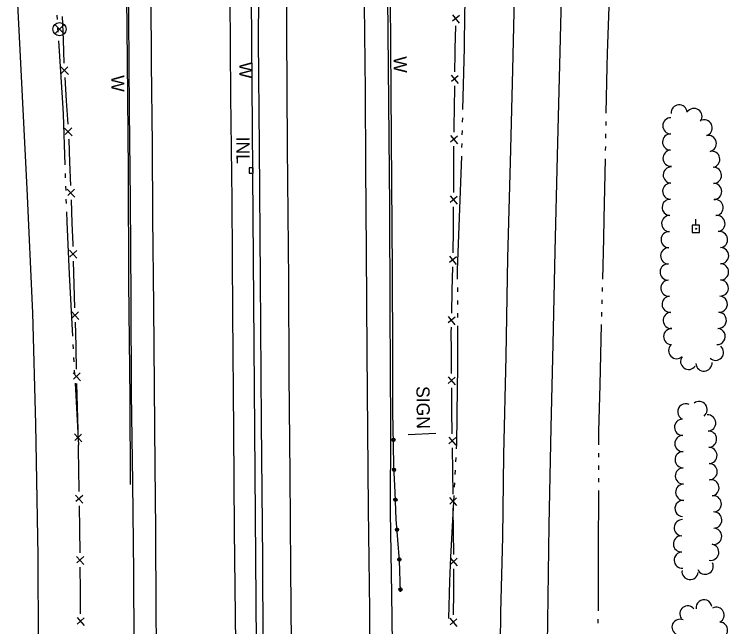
# Model space of a CAD drawing. Extents: x 589250 to 1188077, y 162953 to 363065.
# Drawn here: x 594129.9 to 594456.9, y 169760.3 to 170040.7 of the extents above; entities that cross this region are included whole.
import ezdxf

# ---------------------------------------------------------------- set-up
doc = ezdxf.new("R2010")
doc.units = 0
for name, color, linetype in [('E_BMGRD_P', 7, 'Continuous'), ('E_DRN', 7, 'Continuous'), ('E_DRN_Pipe', 7, 'Continuous'), ('E_DRN_SS_UG', 7, 'Continuous'), ('E_DRN_Text', 7, 'Continuous'), ('E_FEN_P', 7, 'Continuous'), ('E_LAND_TreeLine_P', 7, 'Continuous'), ('E_RDWY', 7, 'Continuous'), ('E_RDWY_Gravel', 7, 'Continuous'), ('E_SGN', 7, 'Continuous'), ('E_SGN_Text', 7, 'Continuous'), ('E_SIG', 7, 'Continuous'), ('E_UTL_EPowerPole', 7, 'Continuous'), ('E_WAL', 7, 'Continuous'), ('E_WAL_Text', 7, 'Continuous'), ('E_WTR_FlowLine', 7, 'Continuous')]:
    doc.layers.add(name, color=color, linetype=linetype)

msp = doc.modelspace()

# ---------------------------------------------------------------- linework, layer by layer
at = {"layer": 'E_BMGRD_P'}
for p, q in [((594303.52, 169843.67), (594303.16, 169858.43)), ((594303.56, 169833.83), (594303.52, 169843.67)), ((594304.24, 169821.84), (594303.56, 169833.83)), ((594304.68, 169809.49), (594304.24, 169821.84)), ((594306.19, 169790.56), (594304.68, 169809.49)), ((594306.67, 169776.16), (594306.19, 169790.56))]:
    msp.add_line(p, q, dxfattribs=at)
for centre, major_axis, ratio in [((594303.47, 169845.84), (0.002, -0.8), 0.911661), ((594303.47, 169845.84), (0.001, -0.403), 0.911661), ((594303.66, 169832.12), (0.023, 0.799), 0.911246), ((594303.66, 169832.12), (0.012, 0.403), 0.911246), ((594304.36, 169818.42), (0.023, 0.799), 0.911373), ((594304.36, 169818.42), (0.011, 0.403), 0.911373), ((594305.06, 169804.71), (0.01, -0.8), 0.911816), ((594305.06, 169804.71), (0.005, -0.403), 0.911816), ((594306.15, 169791.03), (0.01, -0.8), 0.911816), ((594306.15, 169791.03), (0.005, -0.403), 0.911816), ((594306.63, 169777.31), (0.026, -0.799), 0.911732), ((594306.63, 169777.31), (0.013, -0.403), 0.911732)]:
    msp.add_ellipse(centre, major_axis=major_axis, ratio=ratio, dxfattribs=at)
at = {"layer": 'E_DRN'}
for p, q in [((594239.2, 169970.45), (594237.36, 169970.44)), ((594237.36, 169970.44), (594237.38, 169967.95)), ((594239.21, 169967.96), (594239.2, 169970.45)), ((594237.38, 169967.95), (594239.21, 169967.96))]:
    msp.add_line(p, q, dxfattribs=at)
at = {"layer": 'E_DRN_Pipe'}
msp.add_line((594239.14, 169968.53), (594236.28, 170334.67), dxfattribs=at)
at = {"layer": 'E_DRN_SS_UG'}
msp.add_line((594241.45, 169671.17), (594239.14, 169967.85), dxfattribs=at)
at = {"layer": 'E_FEN_P'}
for p, q in [((594330.44, 170040.42), (594333.56, 170036.68)), ((594333.64, 170040.19), (594330.45, 170037.49)), ((594151.83, 170039.72), (594152.22, 170029.02)), ((594331.82, 170035.48), (594331.59, 170024.94)), ((594152.22, 170029.02), (594152.6, 170018.32)), ((594331.59, 170024.94), (594331.54, 170022.66)), ((594331.54, 170022.66), (594331.42, 170014.39)), ((594151.15, 170016.58), (594154.63, 170013.06)), ((594154.4, 170016.61), (594151.4, 170013.61)), ((594152.96, 170011.7), (594153.64, 170001.02)), ((594329.91, 170012.79), (594333.06, 170009.06)), ((594333.11, 170012.57), (594329.93, 170009.85)), ((594331.32, 170007.86), (594331.15, 169997.31)), ((594153.64, 170001.02), (594154.32, 169990.33)), ((594331.15, 169997.31), (594331.04, 169989.97)), ((594152.93, 169988.59), (594156.4, 169985.08)), ((594156.18, 169988.63), (594153.18, 169985.63)), ((594331.04, 169989.97), (594331.02, 169986.76)), ((594329.53, 169985.15), (594332.71, 169981.45)), ((594332.73, 169984.96), (594329.58, 169982.21)), ((594154.74, 169983.72), (594154.78, 169983.15)), ((594154.78, 169983.15), (594155.17, 169973.02)), ((594330.98, 169980.23), (594330.93, 169969.68)), ((594155.17, 169973.02), (594155.59, 169962.32)), ((594330.93, 169969.68), (594330.87, 169959.13)), ((594154.16, 169960.62), (594157.55, 169957.02)), ((594157.41, 169960.58), (594154.34, 169957.65)), ((594155.85, 169955.7), (594156.27, 169945)), ((594329.38, 169957.52), (594332.56, 169953.82)), ((594332.58, 169957.33), (594329.43, 169954.58)), ((594330.83, 169952.6), (594330.77, 169942.57)), ((594156.27, 169945), (594156.64, 169935.46)), ((594330.76, 169942.05), (594330.54, 169931.51)), ((594330.77, 169942.57), (594330.76, 169942.05)), ((594156.64, 169935.46), (594156.68, 169934.31)), ((594155.23, 169932.62), (594158.58, 169928.98)), ((594158.48, 169932.54), (594155.38, 169929.64)), ((594329.03, 169929.91), (594332.15, 169926.17)), ((594332.22, 169929.68), (594329.03, 169926.98)), ((594156.87, 169927.68), (594157.19, 169916.98)), ((594330.4, 169924.98), (594330.17, 169914.43)), ((594157.19, 169916.98), (594157.5, 169906.28)), ((594330.17, 169914.43), (594329.95, 169903.88)), ((594156.05, 169904.59), (594159.4, 169900.96)), ((594159.3, 169904.51), (594156.2, 169901.62)), ((594157.69, 169899.66), (594158.01, 169888.95)), ((594328.44, 169902.29), (594331.56, 169898.55)), ((594331.63, 169902.05), (594328.44, 169899.36)), ((594329.81, 169897.35), (594329.77, 169895.16)), ((594329.77, 169895.16), (594329.83, 169886.8)), ((594158.01, 169888.95), (594158.04, 169887.76)), ((594158.04, 169887.76), (594158.26, 169878.25)), ((594329.83, 169886.8), (594329.91, 169876.25)), ((594156.8, 169876.57), (594160.13, 169872.92)), ((594160.05, 169876.47), (594156.94, 169873.6)), ((594328.44, 169874.62), (594331.67, 169870.97)), ((594331.64, 169874.48), (594328.53, 169871.69)), ((594158.41, 169871.63), (594158.66, 169860.92)), ((594329.95, 169869.72), (594330.01, 169861.88)), ((594158.66, 169860.92), (594158.91, 169850.22)), ((594330.01, 169861.88), (594330.05, 169859.17)), ((594330.05, 169859.17), (594330.18, 169848.63)), ((594157.44, 169848.54), (594160.78, 169844.89)), ((594160.69, 169848.44), (594157.58, 169845.57)), ((594328.73, 169846.98), (594331.97, 169843.35)), ((594331.93, 169846.86), (594328.83, 169844.05)), ((594159.06, 169843.6), (594159.12, 169840.84)), ((594159.12, 169840.84), (594159.25, 169832.89)), ((594330.27, 169842.1), (594330.4, 169831.55)), ((594159.25, 169832.89), (594159.43, 169822.19)), ((594330.4, 169831.55), (594330.54, 169821)), ((594157.95, 169820.52), (594161.26, 169816.84)), ((594161.2, 169820.4), (594158.07, 169817.54)), ((594329.08, 169819.36), (594332.32, 169815.72)), ((594332.28, 169819.23), (594329.18, 169816.43)), ((594159.53, 169815.56), (594159.71, 169804.86)), ((594330.62, 169814.47), (594330.74, 169803.92)), ((594159.71, 169804.86), (594159.88, 169794.15)), ((594330.74, 169803.92), (594330.86, 169793.37)), ((594158.41, 169792.48), (594161.72, 169788.81)), ((594161.66, 169792.36), (594158.53, 169789.51)), ((594329.41, 169791.73), (594332.65, 169788.09)), ((594332.61, 169791.6), (594329.51, 169788.8)), ((594159.96, 169787.53), (594160.03, 169776.82)), ((594330.94, 169786.72), (594330.87, 169776.29)), ((594330.94, 169786.84), (594330.94, 169786.72)), ((594160.03, 169776.82), (594160.11, 169766.11)), ((594330.87, 169776.29), (594330.8, 169765.74)), ((594158.62, 169764.46), (594161.89, 169760.75)), ((594161.87, 169764.31), (594158.7, 169761.48)), ((594329.31, 169764.13), (594332.49, 169760.43)), ((594332.51, 169763.94), (594329.36, 169761.19))]:
    msp.add_line(p, q, dxfattribs=at)
at = {"layer": 'E_LAND_TreeLine_P'}
for centre, radius, start, end in [((594434.21, 169995.57), 3.7, 5.3349, 185.3349), ((594440.97, 169993.88), 3.7, 325.9442, 145.9442), ((594430.4, 169989.64), 3.7, 89.027, 269.027), ((594445.66, 169988.69), 3.7, 285.5571, 105.5571), ((594430.27, 169982.23), 3.7, 89.027, 269.027), ((594447.55, 169981.53), 3.7, 282.2461, 102.2461), ((594430.49, 169974.83), 3.7, 93.3221, 273.3221), ((594449.12, 169974.29), 3.7, 282.2461, 102.2461), ((594430.59, 169967.09), 3.7, 88.1337, 268.1337), ((594449.88, 169966.96), 3.7, 270.9362, 90.9362), ((594430.35, 169959.68), 3.7, 88.1337, 268.1337), ((594450.01, 169959.56), 3.7, 270.9362, 90.9362), ((594430.11, 169952.28), 3.7, 88.1337, 268.1337), ((594450.68, 169952.18), 3.7, 275.8353, 95.8353), ((594429.87, 169944.88), 3.7, 88.1337, 268.1337), ((594451.52, 169944.83), 3.7, 279.0663, 99.0663), ((594429.63, 169937.48), 3.7, 88.1337, 268.1337), ((594452.69, 169937.51), 3.7, 279.0663, 99.0663), ((594429.39, 169930.07), 3.7, 88.1337, 268.1337), ((594453.18, 169930.15), 3.7, 269.8129, 89.8129), ((594429.15, 169922.67), 3.7, 88.1337, 268.1337), ((594453.16, 169922.74), 3.7, 269.8129, 89.8129), ((594453.06, 169915.34), 3.7, 266.3361, 86.3361), ((594429.52, 169915.28), 3.7, 94.1607, 274.1607), ((594430.05, 169907.9), 3.7, 94.1607, 274.1607), ((594452.59, 169907.95), 3.7, 266.3361, 86.3361), ((594430.59, 169900.51), 3.7, 94.1607, 274.1607), ((594452.11, 169900.56), 3.7, 266.3361, 86.3361), ((594430.78, 169893.11), 3.7, 88.2099, 268.2099), ((594451.64, 169893.17), 3.7, 266.3361, 86.3361), ((594433.05, 169886.68), 3.7, 134.2005, 314.2005), ((594450.82, 169885.92), 3.7, 227.9111, 47.9111), ((594438.54, 169881.76), 3.7, 144.9088, 324.9088), ((594445.57, 169881), 3.7, 184.116, 4.116), ((594437.24, 169858.68), 3.72, 64.3711, 244.3711), ((594443.32, 169859.67), 3.72, 307.8061, 127.8061), ((594447.26, 169853.56), 3.72, 272.9111, 92.9111), ((594435.79, 169851.58), 3.72, 90.9362, 270.9362), ((594435.91, 169844.15), 3.72, 90.9362, 270.9362), ((594447.64, 169846.13), 3.72, 272.9111, 92.9111), ((594447.81, 169838.7), 3.72, 270.9362, 90.9362), ((594436.03, 169836.71), 3.72, 90.9362, 270.9362), ((594447.93, 169831.26), 3.72, 270.9362, 90.9362), ((594436.15, 169829.28), 3.72, 90.9362, 270.9362), ((594448.75, 169823.88), 3.72, 278.2419, 98.2419), ((594436.27, 169821.84), 3.72, 90.9362, 270.9362), ((594435.99, 169814.42), 3.72, 86.5375, 266.5375), ((594449.82, 169816.53), 3.72, 278.2419, 98.2419), ((594450.03, 169809.1), 3.72, 270.9362, 90.9362), ((594435.61, 169805.6), 3.72, 87.2448, 267.2448), ((594449.97, 169801.68), 3.72, 259.6263, 79.6263), ((594435.28, 169798.17), 3.72, 92.7261, 272.7261), ((594448.63, 169794.36), 3.72, 259.6263, 79.6263), ((594435.64, 169790.74), 3.72, 92.7261, 272.7261), ((594446.09, 169787.99), 3.72, 204.1348, 24.1348), ((594439.21, 169785.54), 3.72, 173.8112, 353.8112), ((594445.59, 169768.99), 3.62, 9.0663, 189.0663), ((594438.11, 169766.18), 3.62, 37.8061, 217.8061), ((594451.18, 169765.6), 3.62, 297.5012, 117.5012), ((594434.51, 169760.05), 3.62, 65.59, 245.59), ((594452.76, 169758.72), 3.62, 267.3599, 87.3599)]:
    msp.add_arc(centre, radius, start, end, dxfattribs=at)
at = {"layer": 'E_RDWY'}
for p, q in [((594133.1, 170015.26), (594129.89, 170076.56)), ((594254.22, 170077.86), (594254.52, 170032.66)), ((594380.63, 170067.84), (594379.64, 170023.43)), ((594192.32, 170054.05), (594192.55, 170018.28)), ((594358.89, 170054.26), (594357.94, 170015.23)), ((594228.51, 170049.52), (594228.88, 170003.19)), ((594289.99, 170045.02), (594290.5, 170005.63)), ((594254.52, 170032.66), (594254.8, 169979.85)), ((594379.64, 170023.43), (594378.34, 169975.84)), ((594192.55, 170018.28), (594192.94, 169981.06)), ((594135.72, 169960.73), (594133.1, 170015.26)), ((594357.94, 170015.23), (594356.8, 169972.92)), ((594290.5, 170005.63), (594290.64, 169970.91)), ((594228.88, 170003.19), (594229.53, 169955.59)), ((594192.94, 169981.06), (594193.14, 169947.57)), ((594254.8, 169979.85), (594255.36, 169918.86)), ((594378.34, 169975.84), (594377.34, 169932.17)), ((594356.8, 169972.92), (594355.56, 169929.12)), ((594290.64, 169970.91), (594290.99, 169932.09)), ((594138.34, 169904.03), (594135.72, 169960.73)), ((594229.53, 169955.59), (594229.74, 169903.62)), ((594193.14, 169947.57), (594193.58, 169907.07)), ((594290.99, 169932.09), (594291.32, 169886.04)), ((594377.34, 169932.17), (594376.45, 169889.6)), ((594355.56, 169929.12), (594354.83, 169884.1)), ((594255.36, 169918.86), (594255.48, 169875.71)), ((594193.58, 169907.07), (594193.84, 169870.19)), ((594139.81, 169852.95), (594138.34, 169904.03)), ((594229.74, 169903.62), (594230.23, 169850)), ((594376.45, 169889.6), (594375.48, 169851.43)), ((594291.32, 169886.04), (594291.92, 169814.2)), ((594354.83, 169884.1), (594353.86, 169838.96)), ((594255.48, 169875.71), (594256.08, 169829.78)), ((594193.84, 169870.19), (594194.21, 169833.77)), ((594140.79, 169792.72), (594139.81, 169852.95)), ((594375.48, 169851.43), (594374.62, 169806.78)), ((594230.23, 169850), (594230.59, 169804.43)), ((594353.86, 169838.96), (594353.37, 169801.29)), ((594194.21, 169833.77), (594194.46, 169804.8)), ((594256.08, 169829.78), (594256.34, 169787.07)), ((594291.92, 169814.2), (594292.4, 169767.86)), ((594194.46, 169804.8), (594194.62, 169767.13)), ((594374.62, 169806.78), (594373.88, 169762.74)), ((594230.59, 169804.43), (594231.17, 169745.69)), ((594353.37, 169801.29), (594352.47, 169766.79)), ((594141.11, 169738), (594140.79, 169792.72)), ((594256.34, 169787.07), (594256.72, 169737.34)), ((594194.62, 169767.13), (594195.04, 169727.65)), ((594292.4, 169767.86), (594292.59, 169721.1)), ((594352.47, 169766.79), (594352.07, 169730.95)), ((594373.88, 169762.74), (594373.25, 169718.95))]:
    msp.add_line(p, q, dxfattribs=at)
at = {"layer": 'E_RDWY_Gravel'}
for p, q in [((594181.78, 170084.34), (594182.16, 170039.34)), ((594300.66, 170052.32), (594301.14, 170000.36)), ((594182.16, 170039.34), (594182.5, 169996.63)), ((594301.14, 170000.36), (594301.55, 169952.6)), ((594182.5, 169996.63), (594182.93, 169955.6)), ((594182.93, 169955.6), (594183.18, 169910.6)), ((594301.55, 169952.6), (594301.82, 169905.46)), ((594183.18, 169910.6), (594183.41, 169867.04)), ((594301.82, 169905.46), (594302.09, 169851.77)), ((594183.41, 169867.04), (594183.96, 169826.25)), ((594302.09, 169851.77), (594302, 169812.78)), ((594183.96, 169826.25), (594184.4, 169784.86)), ((594302, 169812.78), (594302.49, 169775.26)), ((594184.4, 169784.86), (594184.71, 169743.58)), ((594302.49, 169775.26), (594303.11, 169729.61))]:
    msp.add_line(p, q, dxfattribs=at)
at = {"layer": 'E_SGN'}
msp.add_line((594310.19, 169848.26), (594322.77, 169848.9), dxfattribs=at)
at = {"layer": 'E_SIG'}
for points in [[(594152.66, 170036.01), (594148.47, 170031.77)], [(594148.47, 170035.96), (594152.7, 170031.73)]]:
    msp.add_lwpolyline(points, dxfattribs=at)
msp.add_circle((594150.6, 170033.89), 3, dxfattribs=at)
at = {"layer": 'E_UTL_EPowerPole'}
for points in [[(594441.89, 169944.17), (594441.89, 169946.81)], [(594443.57, 169944.17), (594440.21, 169944.17)], [(594440.21, 169944.17), (594440.21, 169940.81)], [(594443.57, 169940.81), (594443.57, 169944.17)], [(594440.21, 169940.81), (594443.57, 169940.81)]]:
    msp.add_lwpolyline(points, dxfattribs=at)
msp.add_circle((594441.92, 169942.49), 0.217, dxfattribs=at)
at = {"layer": 'E_WAL'}
for p, q in [((594181.02, 170069.84), (594181.48, 170019.57)), ((594241.65, 170049.38), (594241.55, 170028.96)), ((594302.32, 170005.17), (594302.11, 170047.41)), ((594241.55, 170028.96), (594241.92, 169979.9)), ((594181.48, 170019.57), (594181.94, 169968.92)), ((594302.65, 169963.42), (594302.32, 170005.17)), ((594241.92, 169979.9), (594242.46, 169919.76)), ((594181.94, 169968.92), (594182.22, 169917.91)), ((594303.06, 169923.35), (594302.65, 169963.42)), ((594303.09, 169885.07), (594303.06, 169923.35)), ((594242.46, 169919.76), (594242.89, 169853.75)), ((594182.22, 169917.91), (594182.72, 169864.89)), ((594303.16, 169858.43), (594303.09, 169885.07)), ((594182.72, 169864.89), (594183, 169825.39)), ((594242.89, 169853.75), (594243.48, 169791.01)), ((594243.48, 169791.01), (594243.75, 169734.99))]:
    msp.add_line(p, q, dxfattribs=at)
at = {"layer": 'E_WTR_FlowLine'}
for p, q in [((594335.98, 170028.39), (594336.31, 170053.5)), ((594402.28, 170050.44), (594401.33, 170022.92)), ((594149.33, 170040.26), (594149.46, 170038.31)), ((594149.71, 170034.39), (594149.84, 170032.44)), ((594150.09, 170028.52), (594151.93, 170000.15)), ((594335.91, 170025.31), (594335.98, 170028.39)), ((594335.22, 169997.13), (594335.91, 170025.31)), ((594401.33, 170022.92), (594401.12, 170016.86)), ((594401.12, 170016.86), (594400.72, 169995.4)), ((594151.93, 170000.15), (594152.27, 169994.9)), ((594152.27, 169994.9), (594153.03, 169971.74)), ((594335.08, 169991.3), (594335.12, 169993.24)), ((594400.65, 169991.6), (594400.61, 169989.7)), ((594334.93, 169985.47), (594334.98, 169987.41)), ((594400.54, 169985.9), (594400.5, 169984.01)), ((594334.79, 169979.64), (594334.84, 169981.58)), ((594400.43, 169980.21), (594400.4, 169978.31)), ((594333.67, 169947.58), (594334.69, 169975.75)), ((594400.32, 169974.51), (594399.8, 169946.99)), ((594153.16, 169967.82), (594153.22, 169965.86)), ((594153.35, 169961.94), (594153.41, 169959.98)), ((594153.54, 169956.06), (594153.61, 169954.1)), ((594153.73, 169950.18), (594153.88, 169945.59)), ((594153.88, 169945.59), (594155.07, 169921.77)), ((594332.81, 169923.53), (594333.67, 169947.58)), ((594399.8, 169946.99), (594399.63, 169937.97)), ((594399.63, 169937.97), (594399.13, 169919.46)), ((594332.82, 169919.41), (594332.81, 169923.53)), ((594155.07, 169921.77), (594156.49, 169893.37)), ((594332.83, 169913.58), (594332.83, 169915.52)), ((594399.03, 169915.66), (594398.98, 169913.77)), ((594332.84, 169907.74), (594332.84, 169909.69)), ((594398.88, 169909.97), (594398.83, 169908.07)), ((594332.86, 169901.91), (594332.85, 169903.86)), ((594398.73, 169904.28), (594398.67, 169902.38)), ((594332.91, 169878.47), (594332.86, 169898.02)), ((594398.57, 169898.58), (594397.83, 169871.06)), ((594156.7, 169889.46), (594156.81, 169887.5)), ((594157.03, 169883.58), (594157.14, 169881.62)), ((594157.36, 169877.71), (594157.47, 169875.75)), ((594332.78, 169869.84), (594332.91, 169878.47)), ((594157.69, 169871.83), (594159.29, 169843.44)), ((594397.83, 169871.06), (594397.25, 169849.68)), ((594332.41, 169843.81), (594332.78, 169869.83)), ((594397.25, 169849.68), (594397.25, 169843.53)), ((594332.3, 169841.65), (594332.41, 169843.81)), ((594332, 169835.83), (594332.1, 169837.77)), ((594397.24, 169839.74), (594397.24, 169837.84)), ((594397.24, 169834.04), (594397.24, 169832.14)), ((594331.7, 169830), (594331.8, 169831.94)), ((594397.23, 169828.34), (594397.23, 169826.44)), ((594331.4, 169824.18), (594331.5, 169826.12)), ((594397.23, 169822.65), (594397.2, 169795.11)), ((594329.75, 169792.14), (594331.2, 169820.3)), ((594397.2, 169795.11), (594397.18, 169769.42)), ((594329.18, 169781.05), (594329.75, 169792.14)), ((594328.85, 169763.97), (594329.18, 169781.05)), ((594397.18, 169769.42), (594397.12, 169767.58)), ((594397, 169763.79), (594396.94, 169761.89))]:
    msp.add_line(p, q, dxfattribs=at)

# ---------------------------------------------------------------- texts
at = {"layer": 'E_DRN_Text'}
msp.add_text('INL', height=6, rotation=270.2537, dxfattribs=at).set_placement((594231.55, 169984.67))
at = {"layer": 'E_SGN_Text'}
msp.add_text('SIGN', height=6, rotation=270.6314, dxfattribs=at).set_placement((594313.93, 169870.42))
at = {"layer": 'E_WAL_Text'}
for p in [(594303.53, 170021.43), (594232.81, 170018.81), (594174.21, 170012.73)]:
    msp.add_text('W', height=6, rotation=270.6314, dxfattribs=at).set_placement(p)

doc.saveas('drawing.dxf')
